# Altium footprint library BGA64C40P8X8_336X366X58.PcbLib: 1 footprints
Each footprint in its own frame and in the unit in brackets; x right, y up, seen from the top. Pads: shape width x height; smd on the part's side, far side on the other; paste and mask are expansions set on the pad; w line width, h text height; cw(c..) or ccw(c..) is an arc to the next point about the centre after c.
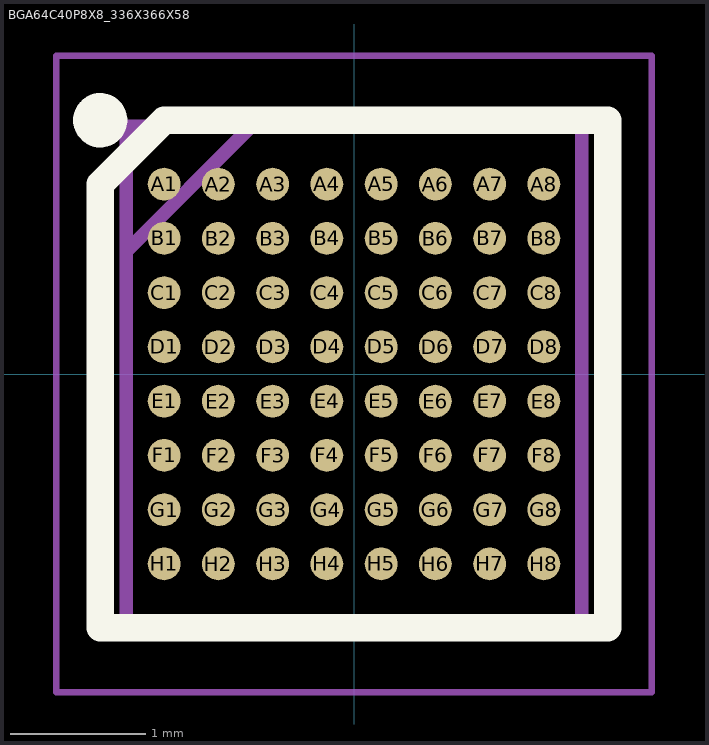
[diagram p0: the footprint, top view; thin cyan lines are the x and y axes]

## BGA64C40P8X8_336X366X58 [mm]
pads (64):
  round 0.242 smd: A1(-1.4,1.4) A2(-1,1.4) A3(-0.6,1.4) A4(-0.2,1.4) A5(0.2,1.4) A6(0.6,1.4) A7(1,1.4) A8(1.4,1.4) B1(-1.4,1) B2(-1,1) B3(-0.6,1) B4(-0.2,1) B5(0.2,1) B6(0.6,1) B7(1,1) B8(1.4,1) C1(-1.4,0.6) C2(-1,0.6) C3(-0.6,0.6) C4(-0.2,0.6) C5(0.2,0.6) C6(0.6,0.6) C7(1,0.6) C8(1.4,0.6) D1(-1.4,0.2) D2(-1,0.2) D3(-0.6,0.2) D4(-0.2,0.2) D5(0.2,0.2) D6(0.6,0.2) D7(1,0.2) D8(1.4,0.2) E1(-1.4,-0.2) E2(-1,-0.2) E3(-0.6,-0.2) E4(-0.2,-0.2) E5(0.2,-0.2) E6(0.6,-0.2) E7(1,-0.2) E8(1.4,-0.2) F1(-1.4,-0.6) F2(-1,-0.6) F3(-0.6,-0.6) F4(-0.2,-0.6) F5(0.2,-0.6) F6(0.6,-0.6) F7(1,-0.6) F8(1.4,-0.6) G1(-1.4,-1) G2(-1,-1) G3(-0.6,-1) G4(-0.2,-1) G5(0.2,-1) G6(0.6,-1) G7(1,-1) G8(1.4,-1) H1(-1.4,-1.4) H2(-1,-1.4) H3(-0.6,-1.4) H4(-0.2,-1.4) H5(0.2,-1.4) H6(0.6,-1.4) H7(1,-1.4) H8(1.4,-1.4)
Top Overlay:
  circle w0.2: c-1.871,1.871 r0.1
  lines w0.2: -1.871,-1.871 1.871,-1.871 1.871,1.871 -1.4,1.871 -1.871,1.4 -1.871,-1.871
Mechanical 15:
  lines w0.1: -1.678,0.906 -0.755,1.829 ; -1.678,-1.829 1.679,-1.829 1.679,1.828 -1.678,1.828 -1.678,-1.829
Mechanical 20:
  lines w0.05: -2.196,-2.346 2.196,-2.346 2.196,2.346 -2.196,2.346 -2.196,-2.346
